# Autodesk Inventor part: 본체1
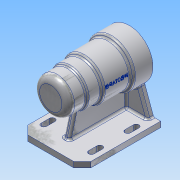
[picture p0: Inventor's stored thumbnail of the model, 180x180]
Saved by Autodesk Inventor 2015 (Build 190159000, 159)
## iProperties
Created: 2017-09
Part Number: 본체1
Material: 알루미늄 6061
Document SubType Name: Modeling
Designer: 김선찬
Density: 2.7 g/cm^3
Appearance: 알루미늄 - 평지
Mass: 693.606 g
Surface Area: 708.752 cm^2
Volume: 256.891 cm^3
Author: 김선찬
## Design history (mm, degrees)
sketch "스케치1"
  geometry: L1 (-56, 8)-(56, 8); L2 (56, 8)-(56, 0); L3 (56, 0)-(-56, 0); L4 (-56, 0)-(-56, 8); L5 (-56, 70)-(56, 70); L6 (-56, 70)-(-56, 95); L7 (-56, 95)-(-31, 95); L8 (-31, 95)-(-31, 97); L9 (-31, 97)-(-11, 97); L10 (-11, 97)-(-11, 100); L11 (-11, 100)-(28, 100); L12 (28, 100)-(28, 104); L13 (28, 104)-(56, 104); L14 (56, 104)-(56, 70); L15 (-50, 70)-(-50, 80.5); L16 (-50, 80.5)-(-47, 80.5); L17 (-47, 80.5)-(-47, 86); L18 (-47, 86)-(-43, 86); L19 (-43, 86)-(-43, 87.5); L20 (-43, 87.5)-(-25, 87.5); L21 (-25, 87.5)-(-25, 91); L22 (-25, 91)-(-13, 91); L23 (-13, 91)-(-13, 94); L24 (-13, 94)-(41, 94); L25 (41, 94)-(41, 91); L26 (41, 91)-(56, 91); L27 (-22.81, 49.76)-(-34, 8); L28 (56, 8)-(56, 49.76); L29 (-22.81, 49.76)-(56, 49.76); 3 further points
  constraints: 58 end point, 20 perpendicular, 4 horizontal, 3 point on line, 2 midpoint, 2 parallel, 2 vertical, 1 coincident, 1 vertical alignment
  dimensions: "d0" = 70 distance from line of point (0, 0) L5; "d1" = 112 distance of L2.end L3.end; "d2" = 112 distance of L5.start L5.end; "d3" = 50 diameter of L7 L5; "d4" = 54 diameter of L9 L5; "d5" = 60 diameter of L11 L5; "d6" = 68 diameter of L13 L5; "d7" = 42 diameter of L26 L5; "d8" = 48 diameter of L24 L5; "d9" = 42 diameter of L22 L5; "d10" = 35 diameter of L20 L5; "d11" = 32 diameter of L18 L5; "d12" = 21 diameter of L16 L5; "d13" = 84 distance between parallel lines of L12 L6; "d14" = 45 distance between parallel lines of L6 L10; "d15" = 25 distance between parallel lines of L6 L8; "d16" = 3 distance between parallel lines of L17 L15; "d17" = 4 distance between parallel lines of L19 L17; "d18" = 18 distance between parallel lines of L21 L19; "d19" = 12 distance between parallel lines of L23 L21; "d20" = 54 distance between parallel lines of L25 L23; "d21" = 15 distance between parallel lines of L14 L25; "d22" = 8 distance between parallel lines of L3 L1; "d23" = 105 deg angle of L1 L27; "d24" = 22 distance from line of L4 L27.end; "d33" = 49.76015 distance between parallel lines of L3 L29
extrude "돌출1" new body sketch "스케치1" stored distance "d25" = 90; taper "d26" = 0 deg
revolve "회전1" stored, may be unused: angle "d27" = 90 deg
fillet "모깎기1" dims "d28" = 3
fillet "모깎기2" dims "d29" = 9
extrude "돌출2" join sketch "스케치1" stored distance "d30" = 8; taper "d31" = 0 deg
revolve "회전2" stored, may be unused: angle "d32" = 90 deg
sketch "스케치2"
  geometry: L1 (66.9, -43.992)-(80, -8); L2 (90, -8)-(49, -8) reference; L3 (90, 0)-(90, -8) reference; A1 r 34 centre (45, -70) between (41, -36.236) and (49, -36.236) reference; 1 further point
  constraints: 2 end point, 1 point on circle, 1 point on line
  dimensions: "d34" = 10 distance from line of L1.end L3; "d35" = 110 deg angle of L2 L1
feature "리브1" sketch "스케치2" dims "d36" = 1, "d37" = 8, "d38" = 0, "d39" = 0, "d40" = 1, "d41" = 1
chamfer "모따기1" distance "d42" = 12; stored, may be unused: second distance "d43" = 2, angle "d44" = 45 deg
sketch "스케치3"
  geometry: L1 (-43.992, 56)-(-104, 56) reference; 3 further points
  constraints: 1 midpoint, 1 vertical alignment, 1 other
  dimensions: "d45" = 48 distance from line of L1 point (-73.996, 8)
feature "엠보싱1" sketch "스케치3" dims "d0" = 70, "d1" = 112, "d2" = 112, "d3" = 50, "d4" = 54, "d5" = 60, "d6" = 68, "d7" = 42, "d8" = 48, "d9" = 42, "d10" = 35, "d11" = 32, "d12" = 21, "d13" = 84, "d14" = 45, "d15" = 25, "d16" = 3, "d17" = 4, "d18" = 18, "d19" = 12, "d20" = 54, "d21" = 15, "d22" = 8, "d23" = 105 deg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
fillet "모깎기3" dims "d48" = 3
fillet "모깎기4" dims "d49" = 0.3
fillet "모깎기5" dims "d50" = 3
chamfer "모따기2" distance "d51" = 1; stored, may be unused: second distance "d52" = 2, angle "d53" = 45 deg
sketch "스케치4"
  geometry: L1 (-30, 54)-(-30, 66); L2 (-26, 54)-(-26, 66); L3 (-34, 66)-(-34, 54); L4 (49, 90)-(-41, 90) reference; L5 (-30, 54)-(-30, 14); L6 (-30, 14)-(-30, 2); L7 (-34, 14)-(-34, 2); L8 (-26, 2)-(-26, 14); A1 r 4 centre (-30, 54) between (-34, 54) and (-26, 54); A2 r 4 centre (-30, 66) between (-26, 66) and (-34, 66); A3 r 4 centre (-30, 14) between (-26, 14) and (-34, 14); A4 r 4 centre (-30, 2) between (-34, 2) and (-26, 2); 3 further points
  constraints: 18 end point, 8 point on circle, 8 tangent, 4 centre point, 2 midpoint, 2 parallel, 2 vertical, 1 point on line
  dimensions: "d54" = 12 distance of L1.start L1.end; "d56" = 4 radius of A2; "d57" = 34 horizontal distance of point (-30, 60) point (4, 34); "d59" = 24 distance from line of L1.end L4; "d68" = 40 distance of L1.start L5.end; "d69" = 12 distance of L5.end L6.end; "d70" = 8 diameter of A4
extrude "돌출3" cut sketch "스케치4" distance "d60" = 8; taper "d61" = 0 deg
sketch "스케치5"
  geometry: C1 r 22 at (45, -70) reference; 2 further points
  constraints: 1 vertical alignment
  dimensions: "d74" = 26 distance of C1.centre point (45, -96)
hole "구멍1" sketch "스케치5" at (45, -96) diameter "d75" = 3.242; stored, may be unused: countersink angle "d79" = 90 deg, drill point angle "d81" = 118 deg; dims "d76" = 8, "d77" = 4, "d78" = 2, "d80" = 11
fillet "모깎기6" dims "d85" = 3
fillet "모깎기7" dims "d86" = 3
fillet "모깎기8" dims "d87" = 3
node "솔리드1"
mirror "대칭1"
pattern_linear "직사각형 패턴1" dims "d64" = 68
pattern_linear "직사각형 패턴2" dims "d67" = 48
pattern_linear "직사각형 패턴3" dims "d73" = 68
pattern_circular "원형 패턴1" dims angle "d83" = 360 deg
